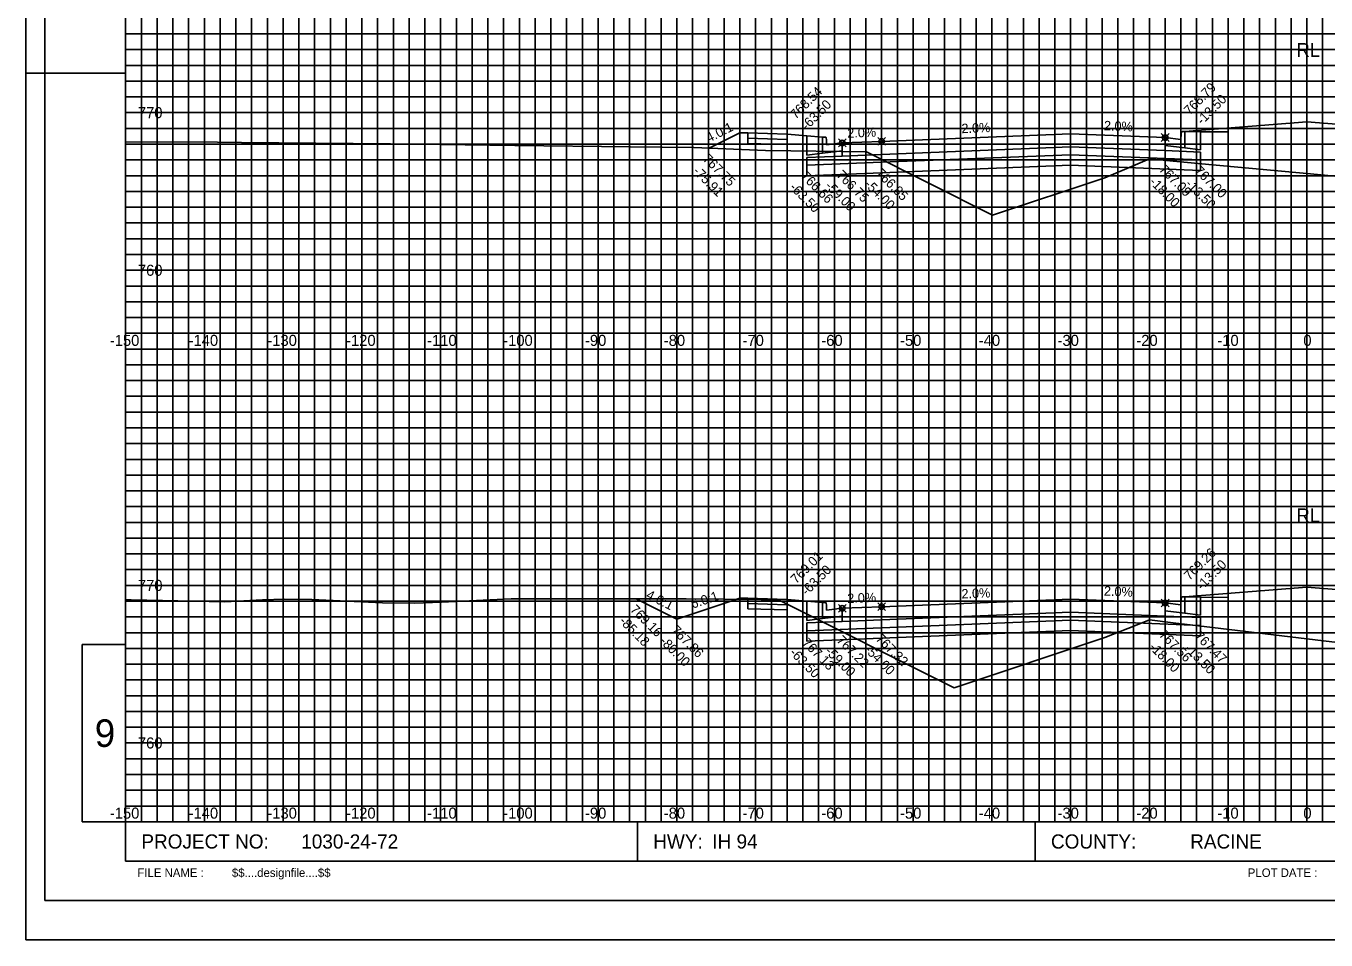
# Model space of a CAD drawing. Extents: x 578243 to 601557, y 174899 to 175559.
# Drawn here: x 599857.2 to 600022.3, y 174898.8 to 175014.8 of the extents above; entities that cross this region are included whole.
import ezdxf

# ---------------------------------------------------------------- set-up
doc = ezdxf.new("R2010")
doc.units = 0
for name, color, linetype in [('E_PROF_Grid', 7, 'Continuous'), ('E_PROF_GridMin', 7, 'Continuous'), ('P_CRDR_Label', 7, 'Continuous'), ('P_CRDR_Link', 7, 'Continuous'), ('P_E_XS_Ground', 7, 'Continuous'), ('P_XS_Text', 7, 'Continuous'), ('PLT_Sheet_Border', 7, 'Continuous'), ('PLT_Sheet_Info', 7, 'Continuous')]:
    doc.layers.add(name, color=color, linetype=linetype)

msp = doc.modelspace()

# ---------------------------------------------------------------- linework, layer by layer
at = {"layer": 'E_PROF_Grid'}
for p, q in [((599879.84, 174913.8), (599879.84, 175108.8)), ((599889.84, 174913.8), (599889.84, 175108.8)), ((599899.84, 174913.8), (599899.84, 175108.8)), ((599909.84, 174913.8), (599909.84, 175108.8)), ((599919.84, 174913.8), (599919.84, 175108.8)), ((599929.84, 174913.8), (599929.84, 175108.8)), ((599939.84, 174913.8), (599939.84, 175108.8)), ((599949.84, 174913.8), (599949.84, 175108.8)), ((599959.84, 174913.8), (599959.84, 175108.8)), ((599969.84, 174913.8), (599969.84, 175108.8)), ((599979.84, 174913.8), (599979.84, 175108.8)), ((599989.84, 174913.8), (599989.84, 175108.8)), ((599999.84, 174913.8), (599999.84, 175108.8)), ((600009.84, 174913.8), (600009.84, 175108.8)), ((600019.84, 174913.8), (600019.84, 175108.8)), ((599869.84, 175013.8), (600184.84, 175013.8)), ((599869.84, 175003.8), (600184.84, 175003.8)), ((599869.84, 174993.8), (600184.84, 174993.8)), ((599869.84, 174983.8), (600184.84, 174983.8)), ((599869.84, 174973.8), (600184.84, 174973.8)), ((599869.84, 174963.8), (600184.84, 174963.8)), ((599869.84, 174953.8), (600184.84, 174953.8)), ((599869.84, 174943.8), (600184.84, 174943.8)), ((599869.84, 174933.8), (600184.84, 174933.8)), ((599869.84, 174923.8), (600184.84, 174923.8))]:
    msp.add_line(p, q, dxfattribs=at)
at = {"layer": 'E_PROF_GridMin'}
for p, q in [((599871.84, 174913.8), (599871.84, 175108.8)), ((599873.84, 174913.8), (599873.84, 175108.8)), ((599875.84, 174913.8), (599875.84, 175108.8)), ((599877.84, 174913.8), (599877.84, 175108.8)), ((599881.84, 174913.8), (599881.84, 175108.8)), ((599883.84, 174913.8), (599883.84, 175108.8)), ((599885.84, 174913.8), (599885.84, 175108.8)), ((599887.84, 174913.8), (599887.84, 175108.8)), ((599891.84, 174913.8), (599891.84, 175108.8)), ((599893.84, 174913.8), (599893.84, 175108.8)), ((599895.84, 174913.8), (599895.84, 175108.8)), ((599897.84, 174913.8), (599897.84, 175108.8)), ((599901.84, 174913.8), (599901.84, 175108.8)), ((599903.84, 174913.8), (599903.84, 175108.8)), ((599905.84, 174913.8), (599905.84, 175108.8)), ((599907.84, 174913.8), (599907.84, 175108.8)), ((599911.84, 174913.8), (599911.84, 175108.8)), ((599913.84, 174913.8), (599913.84, 175108.8)), ((599915.84, 174913.8), (599915.84, 175108.8)), ((599917.84, 174913.8), (599917.84, 175108.8)), ((599921.84, 174913.8), (599921.84, 175108.8)), ((599923.84, 174913.8), (599923.84, 175108.8)), ((599925.84, 174913.8), (599925.84, 175108.8)), ((599927.84, 174913.8), (599927.84, 175108.8)), ((599931.84, 174913.8), (599931.84, 175108.8)), ((599933.84, 174913.8), (599933.84, 175108.8)), ((599935.84, 174913.8), (599935.84, 175108.8)), ((599937.84, 174913.8), (599937.84, 175108.8)), ((599941.84, 174913.8), (599941.84, 175108.8)), ((599943.84, 174913.8), (599943.84, 175108.8)), ((599945.84, 174913.8), (599945.84, 175108.8)), ((599947.84, 174913.8), (599947.84, 175108.8)), ((599951.84, 174913.8), (599951.84, 175108.8)), ((599953.84, 174913.8), (599953.84, 175108.8)), ((599955.84, 174913.8), (599955.84, 175108.8)), ((599957.84, 174913.8), (599957.84, 175108.8)), ((599961.84, 174913.8), (599961.84, 175108.8)), ((599963.84, 174913.8), (599963.84, 175108.8)), ((599965.84, 174913.8), (599965.84, 175108.8)), ((599967.84, 174913.8), (599967.84, 175108.8)), ((599971.84, 174913.8), (599971.84, 175108.8)), ((599973.84, 174913.8), (599973.84, 175108.8)), ((599975.84, 174913.8), (599975.84, 175108.8)), ((599977.84, 174913.8), (599977.84, 175108.8)), ((599981.84, 174913.8), (599981.84, 175108.8)), ((599983.84, 174913.8), (599983.84, 175108.8)), ((599985.84, 174913.8), (599985.84, 175108.8)), ((599987.84, 174913.8), (599987.84, 175108.8)), ((599991.84, 174913.8), (599991.84, 175108.8)), ((599993.84, 174913.8), (599993.84, 175108.8)), ((599995.84, 174913.8), (599995.84, 175108.8)), ((599997.84, 174913.8), (599997.84, 175108.8)), ((600001.84, 174913.8), (600001.84, 175108.8)), ((600003.84, 174913.8), (600003.84, 175108.8)), ((600005.84, 174913.8), (600005.84, 175108.8)), ((600007.84, 174913.8), (600007.84, 175108.8)), ((600011.84, 174913.8), (600011.84, 175108.8)), ((600013.84, 174913.8), (600013.84, 175108.8)), ((600015.84, 174913.8), (600015.84, 175108.8)), ((600017.84, 174913.8), (600017.84, 175108.8)), ((600021.84, 174913.8), (600021.84, 175108.8)), ((599869.84, 175011.8), (600184.84, 175011.8)), ((599869.84, 175009.8), (600184.84, 175009.8)), ((599869.84, 175007.8), (600184.84, 175007.8)), ((599869.84, 175005.8), (600184.84, 175005.8)), ((599869.84, 175001.8), (600184.84, 175001.8)), ((599869.84, 174999.8), (600184.84, 174999.8)), ((599869.84, 174997.8), (600184.84, 174997.8)), ((599869.84, 174995.8), (600184.84, 174995.8)), ((599869.84, 174991.8), (600184.84, 174991.8)), ((599869.84, 174989.8), (600184.84, 174989.8)), ((599869.84, 174987.8), (600184.84, 174987.8)), ((599869.84, 174985.8), (600184.84, 174985.8)), ((599869.84, 174981.8), (600184.84, 174981.8)), ((599869.84, 174979.8), (600184.84, 174979.8)), ((599869.84, 174977.8), (600184.84, 174977.8)), ((599869.84, 174975.8), (600184.84, 174975.8)), ((599869.84, 174971.8), (600184.84, 174971.8)), ((599869.84, 174969.8), (600184.84, 174969.8)), ((599869.84, 174967.8), (600184.84, 174967.8)), ((599869.84, 174965.8), (600184.84, 174965.8)), ((599869.84, 174961.8), (600184.84, 174961.8)), ((599869.84, 174959.8), (600184.84, 174959.8)), ((599869.84, 174957.8), (600184.84, 174957.8)), ((599869.84, 174955.8), (600184.84, 174955.8)), ((599869.84, 174951.8), (600184.84, 174951.8)), ((599869.84, 174949.8), (600184.84, 174949.8)), ((599869.84, 174947.8), (600184.84, 174947.8)), ((599869.84, 174945.8), (600184.84, 174945.8)), ((599869.84, 174941.8), (600184.84, 174941.8)), ((599869.84, 174939.8), (600184.84, 174939.8)), ((599869.84, 174937.8), (600184.84, 174937.8)), ((599869.84, 174935.8), (600184.84, 174935.8)), ((599869.84, 174931.8), (600184.84, 174931.8)), ((599869.84, 174929.8), (600184.84, 174929.8)), ((599869.84, 174927.8), (600184.84, 174927.8)), ((599869.84, 174925.8), (600184.84, 174925.8)), ((599869.84, 174921.8), (600184.84, 174921.8)), ((599869.84, 174919.8), (600184.84, 174919.8)), ((599869.84, 174917.8), (600184.84, 174917.8)), ((599869.84, 174915.8), (600184.84, 174915.8))]:
    msp.add_line(p, q, dxfattribs=at)
at = {"layer": 'P_CRDR_Label'}
for points in [[(600019.84, 175010.26), (600019.84, 175002.63)], [(599960.35, 174999.47), (599961.34, 175000.46)], [(599960.35, 175000.46), (599961.34, 174999.47)], [(599965.35, 174999.67), (599966.34, 175000.66)], [(599965.35, 175000.66), (599966.34, 174999.67)], [(600001.35, 175000.15), (600002.34, 175001.14)], [(600001.35, 175001.14), (600002.34, 175000.15)], [(600019.84, 174951.19), (600019.84, 174943.57)], [(599960.35, 174940.4), (599961.34, 174941.39)], [(599960.35, 174941.39), (599961.34, 174940.4)], [(599965.35, 174940.6), (599966.34, 174941.59)], [(599965.35, 174941.59), (599966.34, 174940.6)], [(600001.35, 174941.08), (600002.34, 174942.07)], [(600001.35, 174942.07), (600002.34, 174941.08)]]:
    msp.add_lwpolyline(points, dxfattribs=at)
for centre in [(599960.84, 174999.96), (599965.84, 175000.16), (600001.84, 175000.64), (599960.84, 174940.9), (599965.84, 174941.1), (600001.84, 174941.58)]:
    msp.add_circle(centre, 0.35, dxfattribs=at)
at = {"layer": 'P_CRDR_Link'}
for points in [[(600004.34, 175001.39), (600019.84, 175002.63)], [(600004.34, 175001.39), (600019.84, 175002.63)], [(600035.34, 175001.39), (600019.84, 175002.63)], [(600035.34, 175001.39), (600019.84, 175002.63)], [(599947.84, 175001.25), (599943.93, 174999.3)], [(599947.84, 175001.25), (599943.93, 174999.3)], [(599948.84, 175001.22), (599947.84, 175001.25)], [(599948.84, 175001.22), (599947.84, 175001.25)], [(599953.84, 175001.07), (599948.84, 175001.22)], [(599953.84, 175001.07), (599948.84, 175001.22)], [(599948.84, 175001.22), (599948.85, 175000.56)], [(599953.84, 175000.41), (599948.85, 175000.56)], [(599948.85, 174999.89), (599948.85, 175000.56)], [(599953.84, 175000.41), (599953.83, 174999.74)], [(599956.34, 175000.87), (599953.84, 175001.07)], [(599956.34, 175000.87), (599953.84, 175001.07)], [(599953.84, 175001.07), (599953.84, 175000.41)], [(599958.34, 175000.71), (599956.34, 175000.87)], [(599956.34, 175000.87), (599956.34, 174998.4)], [(599956.34, 175000.87), (599956.34, 174998.4)], [(599956.34, 175000.87), (599956.34, 174998.4)], [(599958.66, 175000.71), (599958.34, 175000.71)], [(599958.66, 175000.71), (599958.34, 175000.71)], [(599958.34, 175000.71), (599958.34, 174998.65)], [(599958.34, 174998.65), (599958.34, 175000.71)], [(599958.74, 175000.67), (599958.66, 175000.71)], [(599958.74, 175000.67), (599958.66, 175000.71)], [(599958.8, 175000.55), (599958.74, 175000.67)], [(599958.8, 175000.55), (599958.74, 175000.67)], [(599958.83, 175000.39), (599958.8, 175000.55)], [(599958.83, 175000.39), (599958.8, 175000.55)], [(599958.84, 174999.71), (599958.83, 175000.39)], [(599958.84, 174999.71), (599958.83, 175000.39)], [(599989.84, 175001.12), (599965.84, 175000.16)], [(600001.84, 175000.64), (599989.84, 175001.12)], [(599989.84, 175001.12), (599989.84, 174999.46)], [(599989.84, 175001.12), (599989.84, 174999.46)], [(600001.84, 175000.64), (600003.84, 175000.39)], [(600001.84, 175000.64), (600003.84, 175000.39)], [(600001.84, 174999.64), (600001.84, 175000.64)], [(600001.84, 175000.64), (600001.84, 174998.98)], [(600003.84, 175000.39), (600003.86, 175001.07)], [(600003.84, 175000.39), (600003.86, 175001.07)], [(600003.86, 175001.07), (600003.88, 175001.23)], [(600003.86, 175001.07), (600003.88, 175001.23)], [(600003.88, 175001.23), (600003.94, 175001.35)], [(600003.88, 175001.23), (600003.94, 175001.35)], [(600003.94, 175001.35), (600004.02, 175001.39)], [(600003.94, 175001.35), (600004.02, 175001.39)], [(600004.02, 175001.39), (600004.34, 175001.39)], [(600004.02, 175001.39), (600004.34, 175001.39)], [(600004.34, 175001.39), (600004.34, 174999.33)], [(600004.34, 175001.39), (600006.34, 175001.38)], [(600004.34, 174999.33), (600004.34, 175001.39)], [(600006.34, 175001.38), (600006.34, 174999.08)], [(600006.34, 175001.38), (600006.34, 174999.08)], [(600006.34, 175001.38), (600006.34, 174999.08)], [(600006.34, 175001.38), (600009.84, 175001.35)], [(600006.34, 175001.38), (600009.84, 175001.35)], [(599953.83, 174999.74), (599948.85, 174999.89)], [(599956.34, 174998.4), (599958.34, 174998.65)], [(599958.34, 174998.65), (599960.84, 174998.96)], [(599958.34, 174998.65), (599960.84, 174998.96)], [(599960.84, 174999.96), (599958.84, 174999.71)], [(599960.84, 174999.96), (599958.84, 174999.71)], [(599965.84, 175000.16), (599960.84, 174999.96)], [(599960.84, 174999.96), (599960.84, 174998.3)], [(599960.84, 174998.96), (599960.84, 174999.96)], [(599965.84, 175000.16), (599965.84, 174998.5)], [(599965.84, 175000.16), (599965.84, 174998.5)], [(599989.84, 174999.46), (599965.84, 174998.5)], [(600001.84, 174998.98), (599989.84, 174999.46)], [(599989.84, 174999.46), (599989.84, 174998.46)], [(599989.84, 174999.46), (599989.84, 174998.46)], [(600004.34, 174999.33), (600001.84, 174999.64)], [(600004.34, 174999.33), (600001.84, 174999.64)], [(600006.34, 174998.8), (600001.84, 174998.98)], [(600006.34, 174999.08), (600004.34, 174999.33)], [(600006.34, 174998.8), (600006.34, 174997.8)], [(599960.84, 174998.3), (599956.34, 174998.12)], [(599956.34, 174998.12), (599956.34, 174997.12)], [(599965.84, 174997.5), (599956.34, 174997.12)], [(599956.34, 174997.12), (599956.34, 174995.78)], [(599965.84, 174998.5), (599960.84, 174998.3)], [(599965.84, 174998.5), (599965.84, 174997.5)], [(599965.84, 174998.5), (599965.84, 174997.5)], [(599989.84, 174998.46), (599965.84, 174997.5)], [(599965.84, 174997.5), (599965.84, 174996.16)], [(599965.84, 174997.5), (599965.84, 174996.16)], [(599989.84, 174997.12), (599965.84, 174996.16)], [(600006.34, 174997.8), (599989.84, 174998.46)], [(599989.84, 174998.46), (599989.84, 174997.12)], [(599989.84, 174998.46), (599989.84, 174997.12)], [(600006.34, 174996.46), (599989.84, 174997.12)], [(600006.34, 174997.8), (600006.34, 174996.46)], [(599965.84, 174996.16), (599956.34, 174995.78)], [(600004.34, 174942.33), (600019.84, 174943.57)], [(600004.34, 174942.33), (600019.84, 174943.57)], [(600035.34, 174942.33), (600019.84, 174943.57)], [(600035.34, 174942.33), (600019.84, 174943.57)], [(599939.84, 174939.52), (599934.67, 174942.11)], [(599939.84, 174939.52), (599934.67, 174942.11)], [(599947.84, 174942.19), (599939.84, 174939.52)], [(599947.84, 174942.19), (599939.84, 174939.52)], [(599948.84, 174942.16), (599947.84, 174942.19)], [(599948.84, 174942.16), (599947.84, 174942.19)], [(599953.84, 174942.01), (599948.84, 174942.16)], [(599953.84, 174942.01), (599948.84, 174942.16)], [(599948.84, 174942.16), (599948.85, 174941.49)], [(599953.84, 174941.34), (599948.85, 174941.49)], [(599948.85, 174940.83), (599948.85, 174941.49)], [(599953.84, 174941.34), (599953.83, 174940.68)], [(599956.34, 174941.81), (599953.84, 174942.01)], [(599956.34, 174941.81), (599953.84, 174942.01)], [(599953.84, 174942.01), (599953.84, 174941.34)], [(599958.34, 174941.65), (599956.34, 174941.81)], [(599956.34, 174941.81), (599956.34, 174939.34)], [(599956.34, 174941.81), (599956.34, 174939.34)], [(599956.34, 174941.81), (599956.34, 174939.34)], [(599958.66, 174941.65), (599958.34, 174941.65)], [(599958.66, 174941.65), (599958.34, 174941.65)], [(599958.34, 174941.65), (599958.34, 174939.59)], [(599958.34, 174939.59), (599958.34, 174941.65)], [(599958.74, 174941.61), (599958.66, 174941.65)], [(599958.74, 174941.61), (599958.66, 174941.65)], [(599958.8, 174941.49), (599958.74, 174941.61)], [(599958.8, 174941.49), (599958.74, 174941.61)], [(599958.83, 174941.33), (599958.8, 174941.49)], [(599958.83, 174941.33), (599958.8, 174941.49)], [(599958.84, 174940.65), (599958.83, 174941.33)], [(599958.84, 174940.65), (599958.83, 174941.33)], [(599960.84, 174940.9), (599958.84, 174940.65)], [(599960.84, 174940.9), (599958.84, 174940.65)], [(599965.84, 174941.1), (599960.84, 174940.9)], [(599960.84, 174940.9), (599960.84, 174939.23)], [(599960.84, 174939.9), (599960.84, 174940.9)], [(599989.84, 174942.06), (599965.84, 174941.1)], [(599965.84, 174941.1), (599965.84, 174939.43)], [(599965.84, 174941.1), (599965.84, 174939.43)], [(600001.84, 174941.58), (599989.84, 174942.06)], [(599989.84, 174942.06), (599989.84, 174940.39)], [(599989.84, 174942.06), (599989.84, 174940.39)], [(600001.84, 174941.58), (600003.84, 174941.33)], [(600001.84, 174941.58), (600003.84, 174941.33)], [(600001.84, 174940.58), (600001.84, 174941.58)], [(600001.84, 174941.58), (600001.84, 174939.91)], [(600003.84, 174941.33), (600003.86, 174942.01)], [(600003.84, 174941.33), (600003.86, 174942.01)], [(600003.86, 174942.01), (600003.88, 174942.17)], [(600003.86, 174942.01), (600003.88, 174942.17)], [(600003.88, 174942.17), (600003.94, 174942.29)], [(600003.88, 174942.17), (600003.94, 174942.29)], [(600003.94, 174942.29), (600004.02, 174942.33)], [(600003.94, 174942.29), (600004.02, 174942.33)], [(600004.02, 174942.33), (600004.34, 174942.33)], [(600004.02, 174942.33), (600004.34, 174942.33)], [(600004.34, 174942.33), (600004.34, 174940.27)], [(600004.34, 174942.33), (600006.34, 174942.31)], [(600004.34, 174940.27), (600004.34, 174942.33)], [(600006.34, 174942.31), (600006.34, 174940.02)], [(600006.34, 174942.31), (600006.34, 174940.02)], [(600006.34, 174942.31), (600006.34, 174940.02)], [(600006.34, 174942.31), (600009.84, 174942.28)], [(600006.34, 174942.31), (600009.84, 174942.28)], [(599953.83, 174940.68), (599948.85, 174940.83)], [(599956.34, 174939.34), (599958.34, 174939.59)], [(599960.84, 174939.23), (599956.34, 174939.05)], [(599958.34, 174939.59), (599960.84, 174939.9)], [(599958.34, 174939.59), (599960.84, 174939.9)], [(599965.84, 174939.43), (599960.84, 174939.23)], [(599989.84, 174940.39), (599965.84, 174939.43)], [(599965.84, 174939.43), (599965.84, 174938.43)], [(599965.84, 174939.43), (599965.84, 174938.43)], [(599989.84, 174939.39), (599965.84, 174938.43)], [(600001.84, 174939.91), (599989.84, 174940.39)], [(599989.84, 174940.39), (599989.84, 174939.39)], [(599989.84, 174940.39), (599989.84, 174939.39)], [(600006.34, 174938.73), (599989.84, 174939.39)], [(599989.84, 174939.39), (599989.84, 174938.06)], [(599989.84, 174939.39), (599989.84, 174938.06)], [(600004.34, 174940.27), (600001.84, 174940.58)], [(600004.34, 174940.27), (600001.84, 174940.58)], [(600006.34, 174939.73), (600001.84, 174939.91)], [(600006.34, 174940.02), (600004.34, 174940.27)], [(600006.34, 174939.73), (600006.34, 174938.73)], [(599956.34, 174939.05), (599956.34, 174938.05)], [(599965.84, 174938.43), (599956.34, 174938.05)], [(599956.34, 174938.05), (599956.34, 174936.72)], [(599965.84, 174938.43), (599965.84, 174937.1)], [(599965.84, 174938.43), (599965.84, 174937.1)], [(599989.84, 174938.06), (599965.84, 174937.1)], [(600006.34, 174937.4), (599989.84, 174938.06)], [(600006.34, 174938.73), (600006.34, 174937.4)], [(599965.84, 174937.1), (599956.34, 174936.72)]]:
    msp.add_lwpolyline(points, dxfattribs=at)
at = {"layer": 'P_E_XS_Ground'}
for points in [[(599869.84, 175000.1), (599881.49, 175000.04), (599884.57, 175000.02), (599898.72, 174999.87), (599903.46, 174999.83), (599919.26, 174999.65), (599933.96, 174999.47), (599942, 174999.38), (599951.09, 174998.98), (599963.91, 174998.81), (599979.93, 174990.8), (599994.2, 174995.55), (599998.07, 174997.19), (599999.84, 174997.94), (600002.84, 174997.66), (600007.84, 174997.19), (600019.84, 174996.07), (600031.84, 174994.94)], [(599869.84, 174942), (599870.53, 174941.99), (599882.44, 174941.71), (599887.22, 174941.97), (599890.04, 174942.06), (599893.5, 174942.01), (599902.48, 174941.57), (599906.53, 174941.55), (599909.94, 174941.67), (599918.78, 174942.1), (599925, 174942.1), (599929.12, 174942.1), (599933.15, 174942.11), (599941.02, 174942.1), (599950.53, 174942), (599950.69, 174942), (599952.73, 174941.95), (599975.03, 174930.8), (599994.2, 174937.19), (599998.07, 174938.72), (599999.84, 174939.43), (600002.84, 174939.07), (600007.84, 174938.47), (600019.84, 174937.03), (600031.84, 174935.59)]]:
    msp.add_lwpolyline(points, dxfattribs=at)
at = {"layer": 'PLT_Sheet_Border'}
for points in [[(599857.19, 174898.8), (600197.19, 174898.8), (600197.19, 175118.8), (599857.19, 175118.8)], [(599859.59, 174903.8), (600190.59, 174903.8), (600190.59, 175113.8), (599859.59, 175113.8)]]:
    msp.add_lwpolyline(points, close=True, dxfattribs=at)
at = {"layer": 'PLT_Sheet_Info'}
for p, q in [((599869.84, 174908.8), (599869.84, 175108.8)), ((599857.19, 175003.8), (599857.19, 175013.8)), ((599857.19, 175008.8), (599869.84, 175008.8)), ((599869.84, 174913.8), (600184.84, 174913.8)), ((599934.84, 174908.8), (599934.84, 174913.8)), ((599985.34, 174908.8), (599985.34, 174913.8)), ((599857.19, 174898.8), (599857.19, 174908.8)), ((599869.84, 174908.8), (600184.84, 174908.8)), ((599857.19, 174898.8), (599867.19, 174898.8))]:
    msp.add_line(p, q, dxfattribs=at)
msp.add_lwpolyline([(599869.84, 174936.3), (599864.34, 174936.3), (599864.34, 174913.8), (599869.84, 174913.8)], close=True, dxfattribs=at)

# ---------------------------------------------------------------- texts
at = {"layer": 'P_CRDR_Label'}
for p in [(600018.52, 175010.88), (600018.52, 174951.82)]:
    msp.add_text('RL', height=1.75, dxfattribs=at).set_placement(p)
for s, rotation, p in [('768.54', 45, (599954.93, 175002.91)), ('768.79', 45, (600004.93, 175003.42)), ('-63.50', 45, (599956.34, 175001.5)), ('-13.50', 45, (600006.52, 175002.18)), ('4.0:1', 26.5651, (599943.91, 174999.98)), ('2.0%', 2.2906, (599961.5, 175000.61)), ('2.0%', 2.2906, (599976, 175001.19)), ('2.0%', 357.7094, (599994.05, 175001.57)), ('767.75', 315, (599943.08, 174997.82)), ('767.75', 315, (599943.08, 174997.82)), ('767.09', 315, (600000.99, 174996.5)), ('767.00', 315, (600005.49, 174996.32)), ('-75.91', 315, (599941.8, 174996.27)), ('-75.91', 315, (599941.8, 174996.27)), ('766.66', 315, (599955.49, 174995.64)), ('766.75', 315, (599960.03, 174995.78)), ('766.85', 315, (599965.02, 174995.99)), ('-63.50', 315, (599954.08, 174994.22)), ('-59.00', 315, (599958.58, 174994.4)), ('-54.00', 315, (599963.58, 174994.6)), ('-18.00', 315, (599999.76, 174994.91)), ('-13.50', 315, (600004.32, 174994.66)), ('769.01', 45, (599955, 174943.93)), ('769.26', 45, (600004.93, 174944.36)), ('-63.50', 45, (599956.34, 174942.44)), ('-13.50', 45, (600006.52, 174943.12)), ('4.0:1', 333.4349, (599935.83, 174942.22)), ('6.0:1', 18.4349, (599941.85, 174940.84)), ('2.0%', 2.2906, (599961.5, 174941.55)), ('2.0%', 2.2906, (599976, 174942.13)), ('2.0%', 357.7094, (599994.05, 174942.51)), ('769.16', 315, (599933.82, 174940.63)), ('769.16', 315, (599933.82, 174940.63)), ('-85.18', 315, (599932.44, 174939.18)), ('-85.18', 315, (599932.44, 174939.18)), ('767.86', 315, (599939.05, 174937.99)), ('767.32', 315, (599965.02, 174936.93)), ('767.56', 315, (600000.99, 174937.44)), ('767.47', 315, (600005.49, 174937.26)), ('-80.00', 315, (599937.58, 174936.63)), ('767.13', 315, (599955.67, 174936.4)), ('767.22', 315, (599960.03, 174936.72)), ('-54.00', 315, (599963.58, 174935.54)), ('-18.00', 315, (599999.73, 174935.87)), ('-13.50', 315, (600004.26, 174935.66)), ('-63.50', 315, (599954.08, 174935.16)), ('-59.00', 315, (599958.58, 174935.34))]:
    msp.add_text(s, height=1.2, rotation=rotation, dxfattribs=at).set_placement(p)
at = {"layer": 'P_XS_Text'}
for s, p in [('770', (599871.4, 175003.1)), ('760', (599871.4, 174983.1)), ('-150', (599867.84, 174974.2)), ('-140', (599877.84, 174974.2)), ('-130', (599887.84, 174974.2)), ('-120', (599897.84, 174974.2)), ('-110', (599908.13, 174974.2)), ('-100', (599917.79, 174974.2)), ('-90', (599928.17, 174974.2)), ('-80', (599938.18, 174974.2)), ('-70', (599948.18, 174974.2)), ('-60', (599958.18, 174974.2)), ('-50', (599968.18, 174974.2)), ('-40', (599978.18, 174974.2)), ('-30', (599988.18, 174974.2)), ('-20', (599998.18, 174974.2)), ('-10', (600008.47, 174974.2)), ('0', (600019.39, 174974.2)), ('0', (600019.39, 174974.2)), ('770', (599871.4, 174943.1)), ('760', (599871.4, 174923.1)), ('-150', (599867.84, 174914.2)), ('-140', (599877.84, 174914.2)), ('-130', (599887.84, 174914.2)), ('-120', (599897.84, 174914.2)), ('-110', (599908.13, 174914.2)), ('-100', (599917.79, 174914.2)), ('-90', (599928.17, 174914.2)), ('-80', (599938.18, 174914.2)), ('-70', (599948.18, 174914.2)), ('-60', (599958.18, 174914.2)), ('-50', (599968.18, 174914.2)), ('-40', (599978.18, 174914.2)), ('-30', (599988.18, 174914.2)), ('-20', (599998.18, 174914.2)), ('-10', (600008.47, 174914.2)), ('0', (600019.39, 174914.2)), ('0', (600019.39, 174914.2))]:
    msp.add_text(s, height=1.4, rotation=360, dxfattribs=at).set_placement(p)
at = {"layer": 'PLT_Sheet_Info'}
for s, height, p in [('9', 3.5, (599865.92, 174923.3)), ('PROJECT NO:', 1.8, (599871.84, 174910.4)), ('1030-24-72             ', 1.8, (599892.14, 174910.4)), ('HWY:', 1.8, (599936.84, 174910.4)), ('IH 94               ', 1.8, (599944.34, 174910.4)), ('COUNTY:', 1.8, (599987.34, 174910.4)), ('       RACINE       ', 1.8, (600000.34, 174910.4)), ('FILE NAME :', 1.08, (599871.34, 174906.8))]:
    msp.add_text(s, height=height, dxfattribs=at).set_placement(p)
for s, p in [('$$....designfile....$$', (599883.34, 174906.8)), ('PLOT DATE :', (600012.34, 174906.8))]:
    msp.add_text(s, height=1.08, rotation=360, dxfattribs=at).set_placement(p)

doc.saveas('drawing.dxf')
